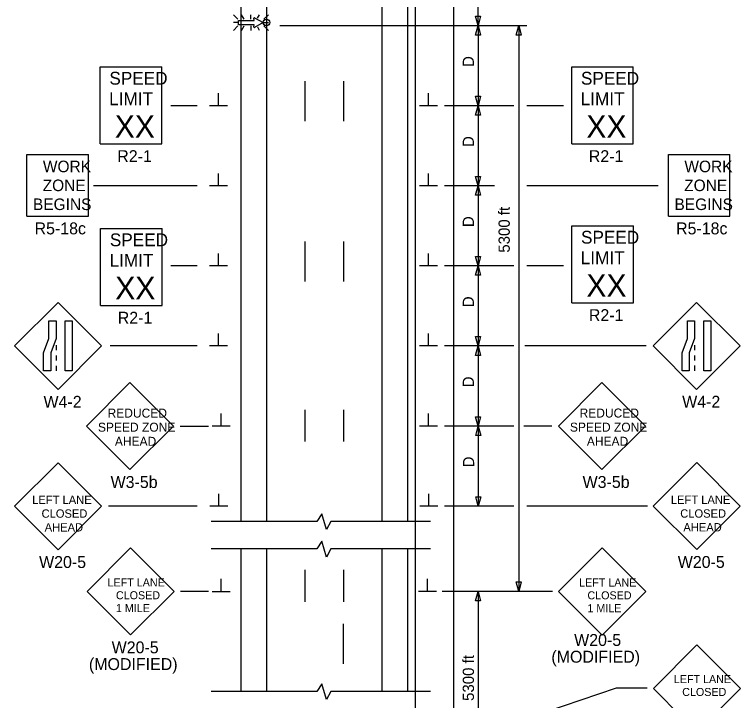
# Model space of a CAD drawing. Extents: x 16590 to 19508, y 5703 to 6974.
# Drawn here: x 16730.7 to 17183.7, y 6134.1 to 6562.3 of the extents above; entities that cross this region are included whole.
import ezdxf

# ---------------------------------------------------------------- set-up
doc = ezdxf.new("R2010")
doc.units = 0
for name, color, linetype in [('ALI_LEGAL_EX', 7, 'Continuous'), ('PAVT_EDGE_EX', 7, 'Continuous'), ('TRAFFIC_SIGNS_PR', 7, 'Continuous'), ('TYPICAL_TEXT_DIMEN_PR', 7, 'Continuous')]:
    doc.layers.add(name, color=color, linetype=linetype)

msp = doc.modelspace()

# ---------------------------------------------------------------- linework, layer by layer
at = {"layer": 'ALI_LEGAL_EX'}
for p, q in [((16980.68, 6974.12), (16980.68, 6155.98)), ((17004.68, 6974.12), (17004.68, 6155.98)), ((16980.68, 6922.21), (16980.68, 6058.3)), ((17004.68, 6922.21), (17004.68, 6058.3))]:
    msp.add_line(p, q, dxfattribs=at)
for points in [[(16911.96, 6520.69), (16911.96, 6495.69)], [(16935.96, 6520.69), (16935.96, 6495.69)], [(16911.96, 6420.69), (16911.96, 6395.69)], [(16935.96, 6420.69), (16935.96, 6395.69)], [(16911.96, 6315.64), (16911.96, 6295.69)], [(16935.96, 6315.64), (16935.96, 6295.69)], [(16911.96, 6215.64), (16911.96, 6195.69)], [(16935.96, 6215.64), (16935.96, 6195.69)], [(16935.96, 6156.97), (16935.96, 6181.97)]]:
    msp.add_lwpolyline(points, dxfattribs=at)
at = {"layer": 'PAVT_EDGE_EX'}
for p, q in [((16871.96, 6927.73), (16871.96, 6245.87)), ((16887.96, 6927.73), (16887.96, 6245.87)), ((16959.96, 6927.73), (16959.96, 6245.87)), ((16975.96, 6927.73), (16975.96, 6245.87)), ((16871.96, 6228.73), (16871.96, 6139.77)), ((16887.96, 6228.73), (16887.96, 6139.78)), ((16959.96, 6228.73), (16959.96, 6139.78)), ((16975.96, 6228.73), (16975.96, 6139.78)), ((16975.96, 6221.78), (16975.96, 6216.94)), ((16887.96, 6218.18), (16887.96, 6216.94))]:
    msp.add_line(p, q, dxfattribs=at)
at = {"layer": 'TRAFFIC_SIGNS_PR'}
for p, q in [((16870.12, 6559.34), (16867.3, 6562.16)), ((16874.07, 6559.34), (16872.44, 6562.16)), ((16878.2, 6559.34), (16878.2, 6562.16)), ((16882.39, 6559.98), (16883.65, 6562.16)), ((16889.11, 6562.16), (16886.29, 6559.34)), ((16870.12, 6557.31), (16867.3, 6557.31)), ((16886.29, 6557.31), (16889.11, 6557.31)), ((16870.12, 6555.28), (16867.3, 6552.46)), ((16872.42, 6552.46), (16874.04, 6555.28)), ((16878.2, 6555.28), (16878.2, 6552.46)), ((16883.67, 6552.46), (16882.47, 6554.55)), ((16889.11, 6552.46), (16886.29, 6555.28)), ((16784.11, 6529.7), (16822.56, 6529.7)), ((16784.11, 6481.64), (16784.11, 6529.7)), ((16822.56, 6481.64), (16822.56, 6529.7)), ((17078.4, 6529.7), (17116.85, 6529.7)), ((17078.4, 6481.64), (17078.4, 6529.7)), ((17116.85, 6481.64), (17116.85, 6529.7)), ((16784.11, 6481.64), (16822.56, 6481.64)), ((17078.4, 6481.64), (17116.85, 6481.64)), ((16738.4, 6436.53), (16738.4, 6474.93)), ((16738.4, 6474.93), (16776.8, 6474.93)), ((16776.8, 6436.53), (16776.8, 6474.93)), ((17138.73, 6436.53), (17138.73, 6474.93)), ((17138.73, 6474.93), (17177.13, 6474.93)), ((17177.13, 6436.53), (17177.13, 6474.93)), ((16738.4, 6436.53), (16776.8, 6436.53)), ((17138.73, 6436.53), (17177.13, 6436.53)), ((16784.41, 6428.82), (16822.86, 6428.82)), ((16784.41, 6380.76), (16784.41, 6428.82)), ((16822.86, 6380.76), (16822.86, 6428.82)), ((17078.43, 6430.45), (17116.88, 6430.45)), ((17078.43, 6382.39), (17078.43, 6430.45)), ((17116.88, 6382.39), (17116.88, 6430.45)), ((16757.84, 6382.57), (16730.69, 6355.42)), ((16785, 6355.42), (16757.84, 6382.57)), ((16784.41, 6380.76), (16822.86, 6380.76)), ((17078.43, 6382.39), (17116.88, 6382.39)), ((17156.39, 6382.61), (17129.23, 6355.46)), ((17183.54, 6355.46), (17156.39, 6382.61)), ((16730.69, 6355.42), (16757.84, 6328.27)), ((16756.6, 6355.91), (16756.6, 6352.71)), ((16757.84, 6328.27), (16785, 6355.42)), ((17129.23, 6355.46), (17156.39, 6328.31)), ((17155.14, 6355.95), (17155.14, 6352.75)), ((17156.39, 6328.31), (17183.54, 6355.46)), ((16756.6, 6349.51), (16756.6, 6346.31)), ((17155.14, 6349.55), (17155.14, 6346.35)), ((16756.6, 6343.11), (16756.6, 6339.91)), ((17155.14, 6343.15), (17155.14, 6339.95)), ((16802.71, 6332.58), (16775.53, 6305.39)), ((16829.9, 6305.39), (16802.71, 6332.58)), ((17097.26, 6332.61), (17070.07, 6305.42)), ((17124.44, 6305.42), (17097.26, 6332.61)), ((16775.53, 6305.39), (16802.71, 6278.2)), ((16802.71, 6278.2), (16829.9, 6305.39)), ((17070.07, 6305.42), (17097.26, 6278.24)), ((17097.26, 6278.24), (17124.44, 6305.42)), ((16757.86, 6282.54), (16730.7, 6255.39)), ((16785.01, 6255.39), (16757.86, 6282.54)), ((17156.43, 6282.58), (17129.27, 6255.43)), ((17183.58, 6255.43), (17156.43, 6282.58)), ((16730.7, 6255.39), (16757.86, 6228.23)), ((16757.86, 6228.23), (16785.01, 6255.39)), ((17129.27, 6255.43), (17156.43, 6228.28)), ((17156.43, 6228.28), (17183.58, 6255.43)), ((16803.16, 6229.35), (16775.97, 6202.17)), ((16830.34, 6202.17), (16803.16, 6229.35)), ((17097.4, 6229.3), (17070.22, 6202.12)), ((17124.59, 6202.12), (17097.4, 6229.3)), ((16775.97, 6202.17), (16803.16, 6174.98)), ((16803.16, 6174.98), (16830.34, 6202.17)), ((17070.22, 6202.12), (17097.4, 6174.93)), ((17097.4, 6174.93), (17124.59, 6202.12)), ((17156.55, 6168.74), (17129.36, 6141.56)), ((17183.73, 6141.56), (17156.55, 6168.74)), ((17129.36, 6141.56), (17156.55, 6114.37)), ((17156.55, 6114.37), (17183.73, 6141.56))]:
    msp.add_line(p, q, dxfattribs=at)
for points in [[(16880.53, 6560.33), (16885.84, 6557.31), (16880.53, 6554.27)], [(16880.03, 6554.63), (16880.26, 6555.93), (16870.54, 6555.93), (16870.54, 6558.67), (16880.26, 6558.67), (16880.03, 6559.97)]]:
    msp.add_lwpolyline(points, dxfattribs=at)
for points in [[(16756.6, 6371.16), (16756.6, 6359.98), (16753.25, 6351.09), (16753.25, 6339.91), (16748.76, 6339.91), (16748.76, 6351.09), (16752.1, 6359.98), (16752.1, 6371.16)], [(16766.73, 6371.16), (16766.73, 6339.91), (16762.24, 6339.91), (16762.24, 6371.16)], [(17155.14, 6371.2), (17155.14, 6360.02), (17151.8, 6351.13), (17151.8, 6339.95), (17147.3, 6339.95), (17147.3, 6351.13), (17150.65, 6360.02), (17150.65, 6371.2)], [(17165.28, 6371.2), (17165.28, 6339.95), (17160.78, 6339.95), (17160.78, 6371.2)]]:
    msp.add_lwpolyline(points, close=True, dxfattribs=at)
msp.add_circle((16887.96, 6557.41), 2, dxfattribs=at)
for centre, start, end in [((16880.37, 6560.03), 61.1084, 189.2692), ((16880.37, 6554.57), 170.0407, 298.5167)]:
    msp.add_arc(centre, 0.341, start, end, dxfattribs=at)
at = {"layer": 'TYPICAL_TEXT_DIMEN_PR'}
for p, q in [((17019.96, 6555.41), (17019.96, 6585.92)), ((17019.96, 6555.41), (17018.39, 6561.27)), ((17018.39, 6561.27), (17019.96, 6561.27)), ((17019.96, 6561.27), (17021.53, 6561.27)), ((17021.53, 6561.27), (17019.96, 6555.41)), ((16896.35, 6555.41), (17050.39, 6555.41)), ((17018.39, 6549.55), (17019.96, 6555.41)), ((17019.96, 6555.41), (17019.96, 6505.41)), ((17019.96, 6555.41), (17021.53, 6549.55)), ((17043.82, 6549.55), (17045.39, 6555.41)), ((17045.39, 6555.41), (17045.39, 6202.2)), ((17045.39, 6555.41), (17046.96, 6549.55)), ((17019.96, 6549.55), (17018.39, 6549.55)), ((17021.53, 6549.55), (17019.96, 6549.55)), ((17045.39, 6549.55), (17043.82, 6549.55)), ((17046.96, 6549.55), (17045.39, 6549.55)), ((16858.07, 6505.41), (16858.07, 6513.19)), ((16989.08, 6505.41), (16989.08, 6513.19)), ((17019.96, 6505.41), (17018.39, 6511.27)), ((17018.39, 6511.27), (17019.96, 6511.27)), ((17019.96, 6511.27), (17021.53, 6511.27)), ((17021.53, 6511.27), (17019.96, 6505.41)), ((16844.64, 6505.41), (16828.16, 6505.41)), ((16863.7, 6505.41), (16852.45, 6505.41)), ((16994.71, 6505.41), (16983.46, 6505.41)), ((17042.19, 6505.41), (16998.96, 6505.41)), ((17018.39, 6499.55), (17019.96, 6505.41)), ((17019.96, 6505.41), (17019.96, 6455.41)), ((17019.96, 6505.41), (17021.53, 6499.55)), ((17073.27, 6505.41), (17050.39, 6505.41)), ((17019.96, 6499.55), (17018.39, 6499.55)), ((17021.53, 6499.55), (17019.96, 6499.55)), ((16858.07, 6455.41), (16858.07, 6463.19)), ((16989.08, 6455.41), (16989.08, 6463.19)), ((17019.96, 6455.41), (17018.39, 6461.27)), ((17018.39, 6461.27), (17019.96, 6461.27)), ((17019.96, 6461.27), (17021.53, 6461.27)), ((17021.53, 6461.27), (17019.96, 6455.41)), ((16844.64, 6455.41), (16780.07, 6455.41)), ((16863.7, 6455.41), (16852.45, 6455.41)), ((16994.71, 6455.41), (16983.46, 6455.41)), ((17030.27, 6455.41), (16998.96, 6455.41)), ((17018.39, 6449.55), (17019.96, 6455.41)), ((17019.96, 6455.41), (17019.96, 6405.41)), ((17019.96, 6455.41), (17021.53, 6449.55)), ((17132.45, 6455.41), (17050.45, 6455.41)), ((17019.96, 6449.55), (17018.39, 6449.55)), ((17021.53, 6449.55), (17019.96, 6449.55)), ((16858.07, 6405.41), (16858.07, 6413.19)), ((16989.08, 6405.41), (16989.08, 6413.19)), ((17019.96, 6405.41), (17018.39, 6411.27)), ((17018.39, 6411.27), (17019.96, 6411.27)), ((17019.96, 6411.27), (17021.53, 6411.27)), ((17021.53, 6411.27), (17019.96, 6405.41)), ((16844.64, 6405.41), (16828.16, 6405.41)), ((16863.7, 6405.41), (16852.45, 6405.41)), ((16994.71, 6405.41), (16983.46, 6405.41)), ((17042.19, 6405.41), (16998.96, 6405.41)), ((17018.39, 6399.55), (17019.96, 6405.41)), ((17019.96, 6405.41), (17019.96, 6355.41)), ((17019.96, 6405.41), (17021.53, 6399.55)), ((17073.27, 6405.41), (17050.39, 6405.41)), ((17019.96, 6399.55), (17018.39, 6399.55)), ((17021.53, 6399.55), (17019.96, 6399.55)), ((16858.07, 6355.41), (16858.07, 6363.19)), ((16989.08, 6355.41), (16989.08, 6363.19)), ((17019.96, 6355.41), (17018.39, 6361.27)), ((17018.39, 6361.27), (17019.96, 6361.27)), ((17019.96, 6361.27), (17021.53, 6361.27)), ((17021.53, 6361.27), (17019.96, 6355.41)), ((16844.64, 6355.41), (16790.39, 6355.41)), ((16863.7, 6355.41), (16852.45, 6355.41)), ((16994.71, 6355.41), (16983.46, 6355.41)), ((17042.19, 6355.41), (16998.96, 6355.41)), ((17018.39, 6349.55), (17019.96, 6355.41)), ((17019.96, 6355.41), (17019.96, 6305.41)), ((17019.96, 6355.41), (17021.53, 6349.55)), ((17124.79, 6355.41), (17049.14, 6355.41)), ((17019.96, 6349.55), (17018.39, 6349.55)), ((17021.53, 6349.55), (17019.96, 6349.55)), ((16859.58, 6305.53), (16859.58, 6313.31)), ((16989.08, 6305.41), (16989.08, 6313.19)), ((17019.96, 6305.41), (17018.39, 6311.27)), ((17018.39, 6311.27), (17019.96, 6311.27)), ((17019.96, 6311.27), (17021.53, 6311.27)), ((17021.53, 6311.27), (17019.96, 6305.41)), ((16833.98, 6305.41), (16851.79, 6305.41)), ((16853.96, 6305.53), (16865.21, 6305.53)), ((16994.71, 6305.41), (16983.46, 6305.41)), ((17042.19, 6305.41), (16998.96, 6305.41)), ((17018.52, 6299.55), (17020.09, 6305.41)), ((17020.09, 6305.41), (17020.09, 6255.41)), ((17020.09, 6305.41), (17021.66, 6299.55)), ((17065.95, 6305.41), (17048.61, 6305.41)), ((17020.09, 6299.55), (17018.52, 6299.55)), ((17021.66, 6299.55), (17020.09, 6299.55)), ((16858.21, 6255.41), (16858.21, 6263.19)), ((16989.22, 6255.41), (16989.22, 6263.19)), ((17020.09, 6255.41), (17018.52, 6261.27)), ((17018.52, 6261.27), (17020.09, 6261.27)), ((17020.09, 6261.27), (17021.66, 6261.27)), ((17021.66, 6261.27), (17020.09, 6255.41)), ((16844.64, 6255.41), (16789.27, 6255.41)), ((16863.83, 6255.41), (16852.58, 6255.41)), ((16994.84, 6255.41), (16983.59, 6255.41)), ((17042.19, 6255.41), (16999.09, 6255.41)), ((17125.66, 6255.41), (17050.45, 6255.41)), ((16922.56, 6250.67), (16919.31, 6245.87)), ((16925.3, 6240.73), (16922.56, 6250.67)), ((16919.31, 6245.87), (16853.36, 6245.87)), ((16928.05, 6245.87), (16925.3, 6240.73)), ((16990.38, 6245.87), (16928.05, 6245.87)), ((16922.56, 6233.53), (16919.31, 6228.73)), ((16925.3, 6223.59), (16922.56, 6233.53)), ((16919.31, 6228.73), (16853.36, 6228.73)), ((16928.05, 6228.73), (16925.3, 6223.59)), ((16990.38, 6228.73), (16928.05, 6228.73)), ((16859.58, 6202.2), (16859.58, 6209.99)), ((16988.33, 6202.2), (16988.33, 6209.99)), ((17045.39, 6202.2), (17043.82, 6208.07)), ((17043.82, 6208.07), (17045.39, 6208.07)), ((17045.39, 6208.07), (17046.97, 6208.07)), ((17046.97, 6208.07), (17045.39, 6202.2)), ((16851.79, 6202.2), (16834.34, 6202.2)), ((16853.96, 6202.2), (16865.21, 6202.2)), ((16993.96, 6202.2), (16982.71, 6202.2)), ((17066.34, 6202.2), (16997.63, 6202.2)), ((17018.39, 6196.34), (17019.96, 6202.2)), ((17019.96, 6202.2), (17019.96, 6102.2)), ((17019.96, 6202.2), (17021.53, 6196.34)), ((17019.96, 6196.34), (17018.39, 6196.34)), ((17021.53, 6196.34), (17019.96, 6196.34)), ((16922.56, 6144.57), (16919.31, 6139.77)), ((16925.3, 6134.63), (16922.56, 6144.57)), ((16919.31, 6139.77), (16853.36, 6139.77)), ((16928.05, 6139.77), (16925.3, 6134.63)), ((16990.38, 6139.77), (16928.05, 6139.77)), ((17026.2, 6114.95), (17106.39, 6141.93)), ((17106.39, 6141.93), (17125.58, 6141.93))]:
    msp.add_line(p, q, dxfattribs=at)

# ---------------------------------------------------------------- texts
at = {"layer": 'TRAFFIC_SIGNS_PR'}
for s, height, p in [('SPEED', 8.01, (16789.89, 6518.55)), ('SPEED', 8.01, (17084.18, 6518.55)), ('LIMIT', 8.01, (16789.73, 6505.73)), ('LIMIT', 8.01, (17084.02, 6505.73)), ('XX', 14.048, (16793.24, 6485.4)), ('XX', 14.048, (17087.53, 6485.4)), ('R2-1', 7.449, (16794.8, 6470.19)), ('R2-1', 7.449, (17089.09, 6470.19)), ('WORK', 7.217, (16748.4, 6463.89)), ('WORK', 7.217, (17148.73, 6463.89)), ('ZONE', 7.217, (16748.28, 6452.08)), ('ZONE', 7.217, (17148.61, 6452.08)), ('BEGINS', 7.217, (16742.21, 6440.27)), ('BEGINS', 7.217, (17142.54, 6440.27)), ('R5-18c', 7.44, (16743.21, 6425.09)), ('R5-18c', 7.44, (17143.54, 6425.09)), ('SPEED', 8.01, (16790.19, 6417.67)), ('SPEED', 8.01, (17084.21, 6419.3)), ('LIMIT', 8.01, (16790.03, 6404.86)), ('LIMIT', 8.01, (17084.05, 6406.48)), ('XX', 14.048, (16793.54, 6384.53)), ('XX', 14.048, (17087.56, 6386.15)), ('R2-1', 7.449, (16795.1, 6369.31)), ('R2-1', 7.449, (17089.12, 6370.94)), ('W4-2', 7.44, (16748.8, 6316.83)), ('W4-2', 7.44, (17147.35, 6316.87)), ('REDUCED', 5.607, (16788.75, 6310.7)), ('REDUCED', 5.607, (17083.3, 6310.74)), ('SPEED ZONE', 5.607, (16782.74, 6301.89)), ('SPEED ZONE', 5.607, (17077.28, 6301.93)), ('AHEAD', 5.607, (16793.31, 6293.08)), ('AHEAD', 5.607, (17087.86, 6293.11)), ('W3-5b', 7.449, (17085.2, 6266.78)), ('W3-5b', 7.449, (16790.65, 6266.75)), ('LEFT LANE', 5.2, (16741.74, 6256.78)), ('LEFT LANE', 5.2, (17140.31, 6256.83)), ('CLOSED', 5.2, (16747.57, 6248.18)), ('CLOSED', 5.2, (17146.14, 6248.23)), ('AHEAD', 5.2, (16749.51, 6239.58)), ('AHEAD', 5.2, (17148.09, 6239.63)), ('W20-5', 7.44, (16746.03, 6216.8)), ('W20-5', 7.44, (17144.6, 6216.84)), ('LEFT LANE', 5.006, (16788.76, 6205.29)), ('LEFT LANE', 5.006, (17083.02, 6205.24)), ('CLOSED', 5.006, (16793.98, 6197.28)), ('CLOSED', 5.006, (17088.23, 6197.23)), ('1 MILE', 5.006, (16793.97, 6189.27)), ('1 MILE', 5.006, (17088.22, 6189.22)), ('W20-5', 7.449, (17079.92, 6168.13)), ('W20-5', 7.449, (16791.31, 6163.53)), ('(MODIFIED)', 7.449, (17065.72, 6157.68)), ('(MODIFIED)', 7.449, (16777.12, 6153.08)), ('LEFT LANE', 5.006, (17142.15, 6144.91)), ('CLOSED', 5.006, (17147.37, 6136.9))]:
    msp.add_text(s, height=height, dxfattribs=at).set_placement(p)
at = {"layer": 'TYPICAL_TEXT_DIMEN_PR'}
for s, p in [('D', (17017.4, 6529.63)), ('D', (17017.4, 6479.63)), ('5300 ft', (17039.76, 6413.65)), ('D', (17017.4, 6429.63)), ('D', (17017.4, 6379.63)), ('D', (17017.4, 6329.63)), ('D', (17017.54, 6279.63)), ('5300 ft', (17017.4, 6133.81))]:
    msp.add_text(s, height=7, rotation=90, dxfattribs=at).set_placement(p)

doc.saveas('drawing.dxf')
